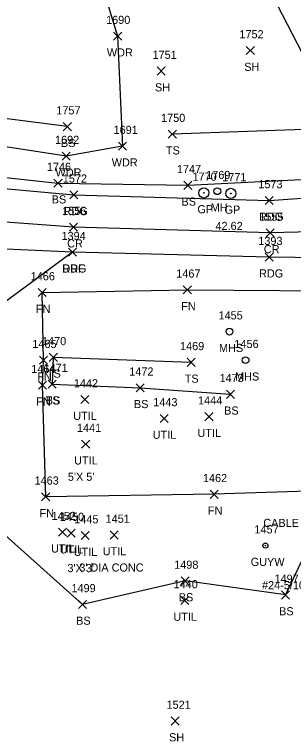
# Model space of a CAD drawing. Extents: x 1609623 to 1616187, y 756677 to 762826.
# Drawn here: x 1610175.1 to 1610243.7, y 761621.4 to 761799.9 of the extents above; entities that cross this region are included whole.
import ezdxf

# ---------------------------------------------------------------- set-up
doc = ezdxf.new("R2010")
doc.units = 0
for name, color, linetype in [('L_A', 7, 'Continuous'), ('L_C', 7, 'Continuous'), ('L_I', 7, 'Continuous'), ('L_TIC', 7, 'Continuous'), ('LAWA', 7, 'Continuous'), ('LELB', 7, 'Continuous'), ('LFNC', 7, 'Continuous'), ('P_A', 7, 'Continuous'), ('P_I', 7, 'Continuous'), ('P_TIC', 7, 'Continuous'), ('PEU', 7, 'Continuous'), ('PRC', 7, 'Continuous'), ('R_A', 7, 'Continuous'), ('R_C', 7, 'Continuous'), ('R_I', 7, 'Continuous'), ('R_TIC', 7, 'Continuous'), ('RDF', 7, 'Continuous'), ('RGP', 7, 'Continuous'), ('U_A', 7, 'Continuous'), ('U_C', 7, 'Continuous'), ('U_I', 7, 'Continuous'), ('UDEFAULT', 7, 'Continuous'), ('UPGW', 7, 'Continuous'), ('USMH', 7, 'Continuous'), ('UUMH', 7, 'Continuous')]:
    doc.layers.add(name, color=color, linetype=linetype)

msp = doc.modelspace()

# ---------------------------------------------------------------- linework, layer by layer
at = {"layer": 'L_TIC'}
for points in [[(1610199.47, 761793.62), (1610201.47, 761795.62)], [(1610201.47, 761793.62), (1610199.47, 761795.62)], [(1610232.12, 761790.09), (1610234.12, 761792.09)], [(1610234.12, 761790.09), (1610232.12, 761792.09)], [(1610210.18, 761785.04), (1610212.18, 761787.04)], [(1610212.18, 761785.04), (1610210.18, 761787.04)], [(1610187.09, 761771.39), (1610189.09, 761773.39)], [(1610189.09, 761771.39), (1610187.09, 761773.39)], [(1610212.94, 761769.55), (1610214.94, 761771.55)], [(1610214.94, 761769.55), (1610212.94, 761771.55)], [(1610200.65, 761766.6), (1610202.65, 761768.6)], [(1610202.65, 761766.6), (1610200.65, 761768.6)], [(1610186.83, 761764.14), (1610188.83, 761766.14)], [(1610188.83, 761764.14), (1610186.83, 761766.14)], [(1610184.8, 761757.52), (1610186.8, 761759.52)], [(1610186.8, 761757.52), (1610184.8, 761759.52)], [(1610216.74, 761756.98), (1610218.74, 761758.98)], [(1610218.74, 761756.98), (1610216.74, 761758.98)], [(1610180.9, 761730.64), (1610182.9, 761732.64)], [(1610182.9, 761730.64), (1610180.9, 761732.64)], [(1610216.63, 761731.3), (1610218.63, 761733.3)], [(1610218.63, 761731.3), (1610216.63, 761733.3)], [(1610181.24, 761714.01), (1610183.24, 761716.01)], [(1610183.24, 761714.01), (1610181.24, 761716.01)], [(1610183.66, 761714.71), (1610185.66, 761716.71)], [(1610185.66, 761714.71), (1610183.66, 761716.71)], [(1610217.57, 761713.48), (1610219.57, 761715.48)], [(1610219.57, 761713.48), (1610217.57, 761715.48)], [(1610180.98, 761707.87), (1610182.98, 761709.87)], [(1610182.98, 761707.87), (1610180.98, 761709.87)], [(1610183.38, 761708.14), (1610185.38, 761710.14)], [(1610185.38, 761708.14), (1610183.38, 761710.14)], [(1610183.38, 761708.14), (1610185.38, 761710.14)], [(1610185.38, 761708.14), (1610183.38, 761710.14)], [(1610205.04, 761707.24), (1610207.04, 761709.24)], [(1610207.04, 761707.24), (1610205.04, 761709.24)], [(1610227.21, 761705.64), (1610229.21, 761707.64)], [(1610229.21, 761705.64), (1610227.21, 761707.64)], [(1610181.78, 761680.45), (1610183.78, 761682.45)], [(1610183.78, 761680.45), (1610181.78, 761682.45)], [(1610223.19, 761681.07), (1610225.19, 761683.07)], [(1610225.19, 761681.07), (1610223.19, 761683.07)], [(1610216.07, 761659.78), (1610218.07, 761661.78)], [(1610218.07, 761659.78), (1610216.07, 761661.78)], [(1610240.74, 761656.34), (1610242.74, 761658.34)], [(1610242.74, 761656.34), (1610240.74, 761658.34)], [(1610190.82, 761654.02), (1610192.82, 761656.02)], [(1610192.82, 761654.02), (1610190.82, 761656.02)], [(1610213.62, 761625.38), (1610215.62, 761627.38)], [(1610215.62, 761625.38), (1610213.62, 761627.38)]]:
    msp.add_lwpolyline(points, dxfattribs=at)
at = {"layer": 'LAWA'}
msp.add_lwpolyline([(1610105.26, 761813.02), (1610140.61, 761813.42), (1610167.68, 761812.65), (1610195.19, 761811.82), (1610200.47, 761794.62), (1610201.65, 761767.6), (1610187.83, 761765.14), (1610147.91, 761771.28), (1610109.49, 761778.29), (1610068.49, 761778.93), (1610059.44, 761777.35), (1610050.54, 761771.19), (1610026.67, 761771.55), (1610012.41, 761775.03), (1609988.62, 761770.46), (1609964.66, 761759.68), (1609934.55, 761749.72), (1609900.52, 761743.76), (1609861.36, 761735.79), (1609834.63, 761731.47), (1609803.94, 761726.14)], dxfattribs=at)
at = {"layer": 'LELB'}
for points in [[(1610188.09, 761772.39), (1610163.62, 761775.55), (1610137.99, 761779.15), (1610110.05, 761784.76), (1610068.13, 761791.39)], [(1610063.27, 761768.93), (1610085.68, 761769.97), (1610116.54, 761765.89), (1610160.06, 761761.31), (1610185.8, 761758.52), (1610217.74, 761757.98), (1610252.18, 761759.72), (1610250.87, 761771.88)], [(1610250.87, 761771.88), (1610213.94, 761770.55)], [(1610331.58, 761719.03), (1610334.04, 761728.28), (1610332.98, 761728.3), (1610331.88, 761725.41), (1610319.31, 761722.82), (1610270.59, 761718.07), (1610241.74, 761657.34), (1610217.07, 761660.78), (1610191.82, 761655.02), (1610167.15, 761677.06), (1610169.37, 761706.02), (1610154.67, 761706.22), (1610148.61, 761677.65)], [(1610218.57, 761714.48), (1610184.66, 761715.71), (1610184.38, 761709.14)], [(1610184.38, 761709.14), (1610206.04, 761708.24), (1610228.21, 761706.64)]]:
    msp.add_lwpolyline(points, dxfattribs=at)
at = {"layer": 'LFNC'}
msp.add_lwpolyline([(1610252.46, 761683.04), (1610224.19, 761682.07), (1610182.78, 761681.45), (1610181.98, 761708.87), (1610182.24, 761715.01), (1610181.9, 761731.64), (1610217.63, 761732.3), (1610251.75, 761732.09)], dxfattribs=at)
at = {"layer": 'P_TIC'}
for points in [[(1610188.68, 761754.64), (1610190.68, 761756.64)], [(1610190.68, 761754.64), (1610188.68, 761756.64)], [(1610236.76, 761753.25), (1610238.76, 761755.25)], [(1610238.76, 761753.25), (1610236.76, 761755.25)], [(1610188.61, 761746.71), (1610190.61, 761748.71)], [(1610190.61, 761746.71), (1610188.61, 761748.71)], [(1610236.99, 761745.29), (1610238.99, 761747.29)], [(1610238.99, 761745.29), (1610236.99, 761747.29)], [(1610188.36, 761740.54), (1610190.36, 761742.54)], [(1610190.36, 761740.54), (1610188.36, 761742.54)], [(1610236.75, 761739.33), (1610238.75, 761741.33)], [(1610238.75, 761739.33), (1610236.75, 761741.33)]]:
    msp.add_lwpolyline(points, dxfattribs=at)
at = {"layer": 'PEU'}
for points in [[(1609803.09, 761712.98), (1609847.46, 761723.55), (1609889.39, 761733.89), (1609939.02, 761747.01), (1609990.56, 761759.58), (1610047.77, 761766.09), (1610098.04, 761763.99), (1610151.67, 761759.1), (1610189.68, 761755.64), (1610237.76, 761754.25), (1610264.31, 761756.11)], [(1610523.28, 761673.99), (1610480.04, 761689.74), (1610439, 761706.13), (1610392.08, 761720.87), (1610334.48, 761734.06), (1610288.63, 761739.63), (1610237.75, 761740.33), (1610189.36, 761741.54), (1610151.21, 761743.29), (1610095.63, 761747.13), (1610049.42, 761749.13), (1609994.68, 761742.82), (1609943, 761732.03), (1609889.61, 761718.43), (1609806.51, 761697.21)]]:
    msp.add_lwpolyline(points, dxfattribs=at)
at = {"layer": 'PRC'}
msp.add_lwpolyline([(1610601.8, 761670.75), (1610582.15, 761672.46), (1610527.05, 761683.5), (1610483.24, 761698.98), (1610440.53, 761715.33), (1610395.01, 761729.94), (1610335.18, 761743.5), (1610288.69, 761747.54), (1610237.99, 761746.29), (1610189.61, 761747.71), (1610150.7, 761750.53), (1610096.59, 761755.33), (1610048.73, 761756.09), (1609993.41, 761750.2), (1609941.26, 761738.94), (1609887.62, 761725.82), (1609805.01, 761705.08)], dxfattribs=at)
at = {"layer": 'R_TIC'}
for points in [[(1610188.36, 761740.54), (1610190.36, 761742.54)], [(1610190.36, 761740.54), (1610188.36, 761742.54)]]:
    msp.add_lwpolyline(points, dxfattribs=at)
at = {"layer": 'RDF'}
for points in [[(1610264.31, 761756.11), (1610264.09, 761770.09), (1610248.38, 761785.61), (1610231.28, 761818.76)], [(1610189.36, 761741.54), (1610170.1, 761727.36), (1610123.54, 761709.71), (1610082.66, 761698.89), (1610034.71, 761691.02), (1609986.1, 761683.34), (1609933.94, 761672.88), (1609882.6, 761661.03), (1609815.24, 761649.06)]]:
    msp.add_lwpolyline(points, dxfattribs=at)
at = {"layer": 'RGP'}
for p, q in [((1610221.66, 761756.1), (1610221.66, 761756.1)), ((1610228.32, 761755.99), (1610228.32, 761755.99))]:
    msp.add_line(p, q, dxfattribs=at)
for centre, radius in [((1610221.66, 761756.1), 1.25), ((1610228.32, 761755.99), 1.25), ((1610221.66, 761756.1), 0.0833), ((1610228.32, 761755.99), 0.0833)]:
    msp.add_circle(centre, radius, dxfattribs=at)
at = {"layer": 'UDEFAULT'}
for points in [[(1610191.39, 761704.34), (1610193.39, 761706.34)], [(1610193.39, 761704.34), (1610191.39, 761706.34)], [(1610210.94, 761699.7), (1610212.94, 761701.7)], [(1610212.94, 761699.7), (1610210.94, 761701.7)], [(1610221.94, 761700.14), (1610223.94, 761702.14)], [(1610223.94, 761700.14), (1610221.94, 761702.14)], [(1610191.61, 761693.39), (1610193.61, 761695.39)], [(1610193.61, 761693.39), (1610191.61, 761695.39)], [(1610185.94, 761671.75), (1610187.94, 761673.75)], [(1610187.94, 761671.75), (1610185.94, 761673.75)], [(1610188.06, 761671.54), (1610190.06, 761673.54)], [(1610190.06, 761671.54), (1610188.06, 761673.54)], [(1610191.51, 761670.94), (1610193.51, 761672.94)], [(1610193.51, 761670.94), (1610191.51, 761672.94)], [(1610198.64, 761671.08), (1610200.64, 761673.08)], [(1610200.64, 761671.08), (1610198.64, 761673.08)], [(1610216.01, 761654.99), (1610218.01, 761656.99)], [(1610218.01, 761654.99), (1610216.01, 761656.99)]]:
    msp.add_lwpolyline(points, dxfattribs=at)
at = {"layer": 'UPGW'}
for radius in [0.625, 0.0833]:
    msp.add_circle((1610236.8, 761669.46), radius, dxfattribs=at)
at = {"layer": 'USMH'}
for p, q in [((1610227.99, 761722.03), (1610227.99, 761722.03)), ((1610228.82, 761722.03), (1610228.82, 761722.03)), ((1610231.94, 761715.01), (1610231.94, 761715.01)), ((1610232.78, 761715.01), (1610232.78, 761715.01))]:
    msp.add_line(p, q, dxfattribs=at)
for centre in [(1610227.99, 761722.03), (1610231.94, 761715.01)]:
    msp.add_circle(centre, 0.833, dxfattribs=at)
at = {"layer": 'UUMH'}
for p, q in [((1610224.99, 761756.52), (1610224.99, 761756.52)), ((1610225.83, 761756.52), (1610225.83, 761756.52))]:
    msp.add_line(p, q, dxfattribs=at)
msp.add_circle((1610224.99, 761756.52), 0.833, dxfattribs=at)

# ---------------------------------------------------------------- texts
at = {"layer": 'L_A'}
for s, p in [('WDR', (1610197.83, 761789.62)), ('SH', (1610231.61, 761786.09)), ('SH', (1610209.66, 761781.04)), ('BS', (1610186.53, 761767.39)), ('TS', (1610212.35, 761765.55)), ('WDR', (1610199.02, 761762.6)), ('WDR', (1610185.19, 761760.14)), ('BS', (1610184.25, 761753.52)), ('BS', (1610216.18, 761752.98)), ('FN', (1610180.38, 761726.64)), ('FN', (1610216.11, 761727.3)), ('TS', (1610183.07, 761710.71)), ('FN', (1610180.72, 761710.01)), ('TS', (1610216.98, 761709.48)), ('FN', (1610180.46, 761703.87)), ('TS', (1610182.79, 761704.14)), ('BS', (1610182.82, 761704.14)), ('BS', (1610204.48, 761703.24)), ('BS', (1610226.66, 761701.64)), ('FN', (1610181.26, 761676.45)), ('FN', (1610222.67, 761677.07)), ('BS', (1610215.51, 761655.78)), ('BS', (1610240.18, 761652.34)), ('BS', (1610190.26, 761650.02)), ('SH', (1610213.11, 761621.38))]:
    msp.add_text(s, height=2, dxfattribs=at).set_placement(p)
at = {"layer": 'L_C'}
msp.add_text('CABLE & WOOD POST', height=2, dxfattribs=at).set_placement((1610236.29, 761674.04))
at = {"layer": 'L_I'}
for s, p in [('1690', (1610197.64, 761797.62)), ('1752', (1610230.42, 761794.09)), ('1751', (1610209.05, 761789.04)), ('1757', (1610185.39, 761775.39)), ('1750', (1610211.16, 761773.55)), ('1691', (1610199.48, 761770.6)), ('1692', (1610185.09, 761768.14)), ('1746', (1610183.06, 761761.52)), ('1747', (1610215.05, 761760.98)), ('1467', (1610214.89, 761735.3)), ('1466', (1610179.1, 761734.64)), ('1465', (1610179.5, 761718.01)), ('1470', (1610181.88, 761718.71)), ('1469', (1610215.82, 761717.48)), ('1464', (1610179.24, 761711.87)), ('1471', (1610182.25, 761712.14)), ('1471', (1610182.25, 761712.14)), ('1472', (1610203.34, 761711.24)), ('1473', (1610225.52, 761709.64)), ('1462', (1610221.45, 761685.07)), ('1463', (1610180.04, 761684.45)), ('1498', (1610214.38, 761663.78)), ('1497', (1610239.05, 761660.34)), ('1499', (1610189.12, 761658.02)), ('1521', (1610212.5, 761629.38))]:
    msp.add_text(s, height=2, dxfattribs=at).set_placement(p)
at = {"layer": 'P_A'}
for s, p in [('RDG', (1610187.17, 761750.64)), ('RDG', (1610235.25, 761749.25)), ('CR', (1610188.05, 761742.71)), ('CR', (1610236.42, 761741.29)), ('RDG', (1610186.85, 761736.54)), ('RDG', (1610235.24, 761735.33))]:
    msp.add_text(s, height=2, dxfattribs=at).set_placement(p)
at = {"layer": 'P_I'}
for s, p in [('1572', (1610186.99, 761758.64)), ('1573', (1610235.07, 761757.25)), ('1556', (1610186.86, 761750.71)), ('1555', (1610235.3, 761749.29)), ('1394', (1610186.67, 761744.54)), ('1393', (1610235.06, 761743.33))]:
    msp.add_text(s, height=2, dxfattribs=at).set_placement(p)
at = {"layer": 'R_A'}
for s, p in [('GP', (1610220.1, 761751.1)), ('GP', (1610226.76, 761750.99)), ('DRF', (1610186.9, 761736.54))]:
    msp.add_text(s, height=2, dxfattribs=at).set_placement(p)
at = {"layer": 'R_C'}
msp.add_text('42.62', height=2, dxfattribs=at).set_placement((1610224.53, 761746.99))
at = {"layer": 'R_I'}
for s, p in [('1770', (1610218.88, 761759.1)), ('1771', (1610226.2, 761758.99)), ('1394', (1610186.67, 761744.54))]:
    msp.add_text(s, height=2, dxfattribs=at).set_placement(p)
at = {"layer": 'U_A'}
for s, p in [('MH', (1610223.36, 761751.52)), ('MHS', (1610225.4, 761717.03)), ('MHS', (1610229.36, 761710.01)), ('UTIL', (1610189.55, 761700.34)), ('UTIL', (1610220.11, 761696.14)), ('UTIL', (1610209.1, 761695.7)), ('UTIL', (1610189.77, 761689.39)), ('UTIL', (1610184.11, 761667.75)), ('UTIL', (1610186.23, 761667.54)), ('UTIL', (1610189.67, 761666.94)), ('UTIL', (1610196.81, 761667.08)), ('GUYW', (1610233.2, 761664.46)), ('UTIL', (1610214.18, 761650.99))]:
    msp.add_text(s, height=2, dxfattribs=at).set_placement(p)
at = {"layer": 'U_C'}
for s, p in [("5'X 5'", (1610188.24, 761685.39)), ("3'X 3'", (1610188.14, 761662.94)), ("3' DIA CONC", (1610191.05, 761663.08)), ('#24-5/10/8-2-1/1 TIE=71.04', (1610235.98, 761658.75))]:
    msp.add_text(s, height=2, dxfattribs=at).set_placement(p)
at = {"layer": 'U_I'}
for s, p in [('1769', (1610222.25, 761759.52)), ('1455', (1610225.29, 761725.03)), ('1456', (1610229.19, 761718.01)), ('1442', (1610189.7, 761708.34)), ('1443', (1610209.24, 761703.7)), ('1444', (1610220.25, 761704.14)), ('1441', (1610190.48, 761697.39)), ('1452', (1610184.25, 761675.75)), ('1450', (1610186.28, 761675.54)), ('1445', (1610189.81, 761674.94)), ('1451', (1610197.52, 761675.08)), ('1457', (1610234.11, 761672.46)), ('1440', (1610214.24, 761658.99))]:
    msp.add_text(s, height=2, dxfattribs=at).set_placement(p)

doc.saveas('drawing.dxf')
